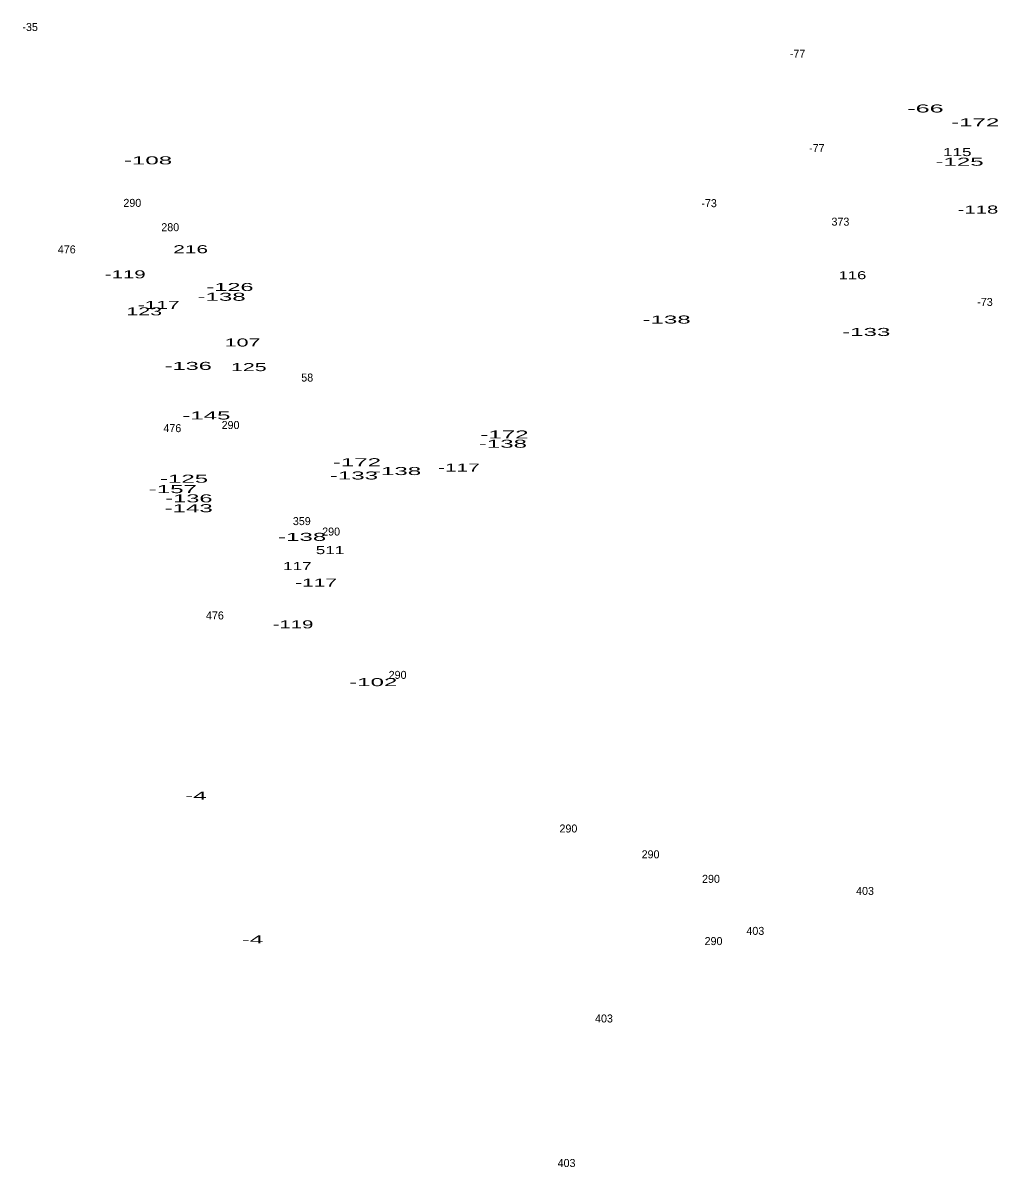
# Model space of a CAD drawing. Extents: x -662280 to -658689, y -991723 to -987042.
# Drawn here: x -661434 to -660947, y -991723 to -991151 of the extents above; entities that cross this region are included whole.
import ezdxf
from ezdxf.enums import TextEntityAlignment as Align

# ---------------------------------------------------------------- set-up
doc = ezdxf.new("R2010")
doc.units = 0
doc.header["$LTSCALE"] = 1.6
doc.layers.add('24', color=7, linetype='Continuous')

msp = doc.modelspace()

# ---------------------------------------------------------------- texts
at = {"layer": '24'}
for s, p in [('-35', (-661430.795, -991155.15)), ('-77', (-661047.235, -991168.51)), ('-77', (-661037.615, -991215.69)), ('290', (-661379.727, -991243.06)), ('-73', (-661091.451, -991243.19)), ('280', (-661360.781, -991255.21)), ('373', (-661025.813, -991252.44)), ('476', (-661412.493, -991266.3)), ('-73', (-660953.551, -991292.57)), ('58', (-661292.307, -991330.36)), ('476', (-661359.733, -991355.66)), ('290', (-661330.627, -991354.09)), ('359', (-661295.023, -991402.11)), ('290', (-661280.357, -991407.34)), ('476', (-661338.453, -991449.28)), ('290', (-661247.137, -991478.98)), ('290', (-661161.757, -991555.75)), ('290', (-661120.697, -991568.66)), ('290', (-661090.507, -991580.92)), ('403', (-661013.525, -991586.97)), ('403', (-661068.345, -991606.94)), ('290', (-661089.227, -991612.03)), ('403', (-661143.985, -991650.71)), ('403', (-661162.685, -991722.95))]:
    msp.add_text(s, height=4, dxfattribs=at).set_placement(p, align=Align.CENTER)
for s, width, p in [('-66', 2.35, (-660983.313, -991195.87)), ('-172', 2.25, (-660958.435, -991202.8)), ('115', 1.6, (-660967.424, -991217.67)), ('-108', 2.25, (-661371.877, -991221.81)), ('-125', 2.25, (-660966.271, -991222.49)), ('-118', 1.9, (-660957.067, -991246.38)), ('216', 1.95, (-661350.573, -991266.22)), ('-119', 1.9, (-661383.251, -991278.78)), ('116', 1.55, (-661019.799, -991279.2)), ('-126', 2.2, (-661330.925, -991285.1)), ('-117', 1.95, (-661366.541, -991294.07)), ('-138', 2.25, (-661335.121, -991289.98)), ('123', 2, (-661373.787, -991297.28)), ('-138', 2.25, (-661112.691, -991301.37)), ('-133', 2.25, (-661012.901, -991307.56)), ('107', 2, (-661324.639, -991312.84)), ('-136', 2.2, (-661351.755, -991324.54)), ('125', 2, (-661321.507, -991325.14)), ('-145', 2.25, (-661342.706, -991349.32)), ('-138', 2.25, (-661194.511, -991363.44)), ('-172', 2.25, (-661193.745, -991358.82)), ('-172', 2.25, (-661267.465, -991372.69)), ('-125', 2.25, (-661353.881, -991380.92)), ('-133', 2.25, (-661268.951, -991379.31)), ('-138', 2.25, (-661247.401, -991377.1)), ('-117', 1.95, (-661216.501, -991375.36)), ('-157', 2.25, (-661359.465, -991386.12)), ('-136', 2.2, (-661351.435, -991390.74)), ('-143', 2.25, (-661351.566, -991395.66)), ('-138', 2.25, (-661294.851, -991409.98)), ('511', 1.6, (-661280.894, -991416.61)), ('117', 1.6, (-661297.259, -991424.59)), ('-117', 1.95, (-661287.881, -991432.86)), ('-119', 1.9, (-661299.391, -991453.72)), ('-102', 2.25, (-661259.307, -991482.61)), ('-4', 2.25, (-661347.95, -991539.37)), ('-4', 2.25, (-661319.62, -991611.22))]:
    msp.add_text(s, height=4, dxfattribs=dict(at, width=width)).set_placement(p, align=Align.CENTER)

doc.saveas('drawing.dxf')
